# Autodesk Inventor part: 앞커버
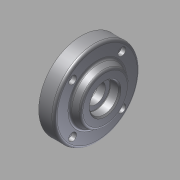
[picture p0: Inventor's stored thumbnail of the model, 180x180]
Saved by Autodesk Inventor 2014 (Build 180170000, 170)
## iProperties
Company: 한국ATC센터
Created: 2015-12
Part Number: 앞커버
Document SubType Name: Modeling
Designer: 앞커버
Density: 1 g/cm^3
Mass: 42.1916 g
Surface Area: 117.889 cm^2
Volume: 42.1916 cm^3
Material: 일반
Appearance: 기본값
Author: mdu
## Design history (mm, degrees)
sketch "스케치1"
  geometry: L1 (-11.5, 0)-(11.5, 0); L2 (11.5, 0)-(11.5, 22.5); L3 (11.5, 22.5)-(6.5, 22.5); L4 (6.5, 22.5)-(6.5, 32.5); L5 (6.5, 32.5)-(-5.5, 32.5); L6 (-5.5, 32.5)-(-5.5, 21); L7 (-5.5, 21)-(-11.5, 18.202); L8 (-11.5, 18.202)-(-11.5, 0); 2 further points
  constraints: 16 end point, 3 parallel, 3 perpendicular, 1 coincident, 1 horizontal, 1 midpoint
  dimensions: "d0" = 23 distance of L1.start L1.end; "d1" = 65 diameter of L5 L1; "d2" = 45 diameter of L3 L1; "d3" = 42 diameter of L6.end L1; "d4" = 115 deg angle of L7 L6; "d5" = 12 distance of L4.end L5.end; "d6" = 5 distance of L2.end L3.end
revolve "회전1" sketch "스케치1" stored, may be unused: angle "d7" = 90 deg
sketch "스케치2"
  geometry: L1 (0, 0)-(32.5, 0); L2 (0, 0)-(18.738, 18.738); 1 further point
  constraints: 4 end point, 1 horizontal, 1 horizontal alignment, 1 other
  dimensions: "d8" = 45 deg angle of L1 L2; "d9" = 26.5 distance of L1.start L2.end
hole "구멍1" sketch "스케치2" at (18.738, 18.738) diameter "d10" = 3.4; stored, may be unused: countersink angle "d14" = 90 deg, drill point angle "d16" = 118 deg; dims "d11" = 6, "d12" = 6, "d13" = 3.3, "d15" = 8
fillet "모깎기1" dims "d20" = 2
hole "구멍2" diameter "d23" = 15; stored, may be unused: countersink angle "d27" = 90 deg, drill point angle "d29" = 118 deg; dims "d21" = 10, "d22" = 10, "d24" = 6, "d25" = 32, "d26" = 10, "d28" = 8
hole "구멍3" diameter "d32" = 22; stored, may be unused: countersink angle "d36" = 90 deg, drill point angle "d38" = 0 deg; dims "d30" = 10, "d31" = 10, "d33" = 6, "d34" = 32, "d35" = 10, "d37" = 7.3
chamfer "모따기1" distance "d39" = 1; stored, may be unused: second distance "d40" = 2, angle "d41" = 45 deg
fillet "모깎기2" dims "d42" = 0.3
node "솔리드1"
pattern_circular "원형 패턴1" dims angle "d18" = 360 deg
